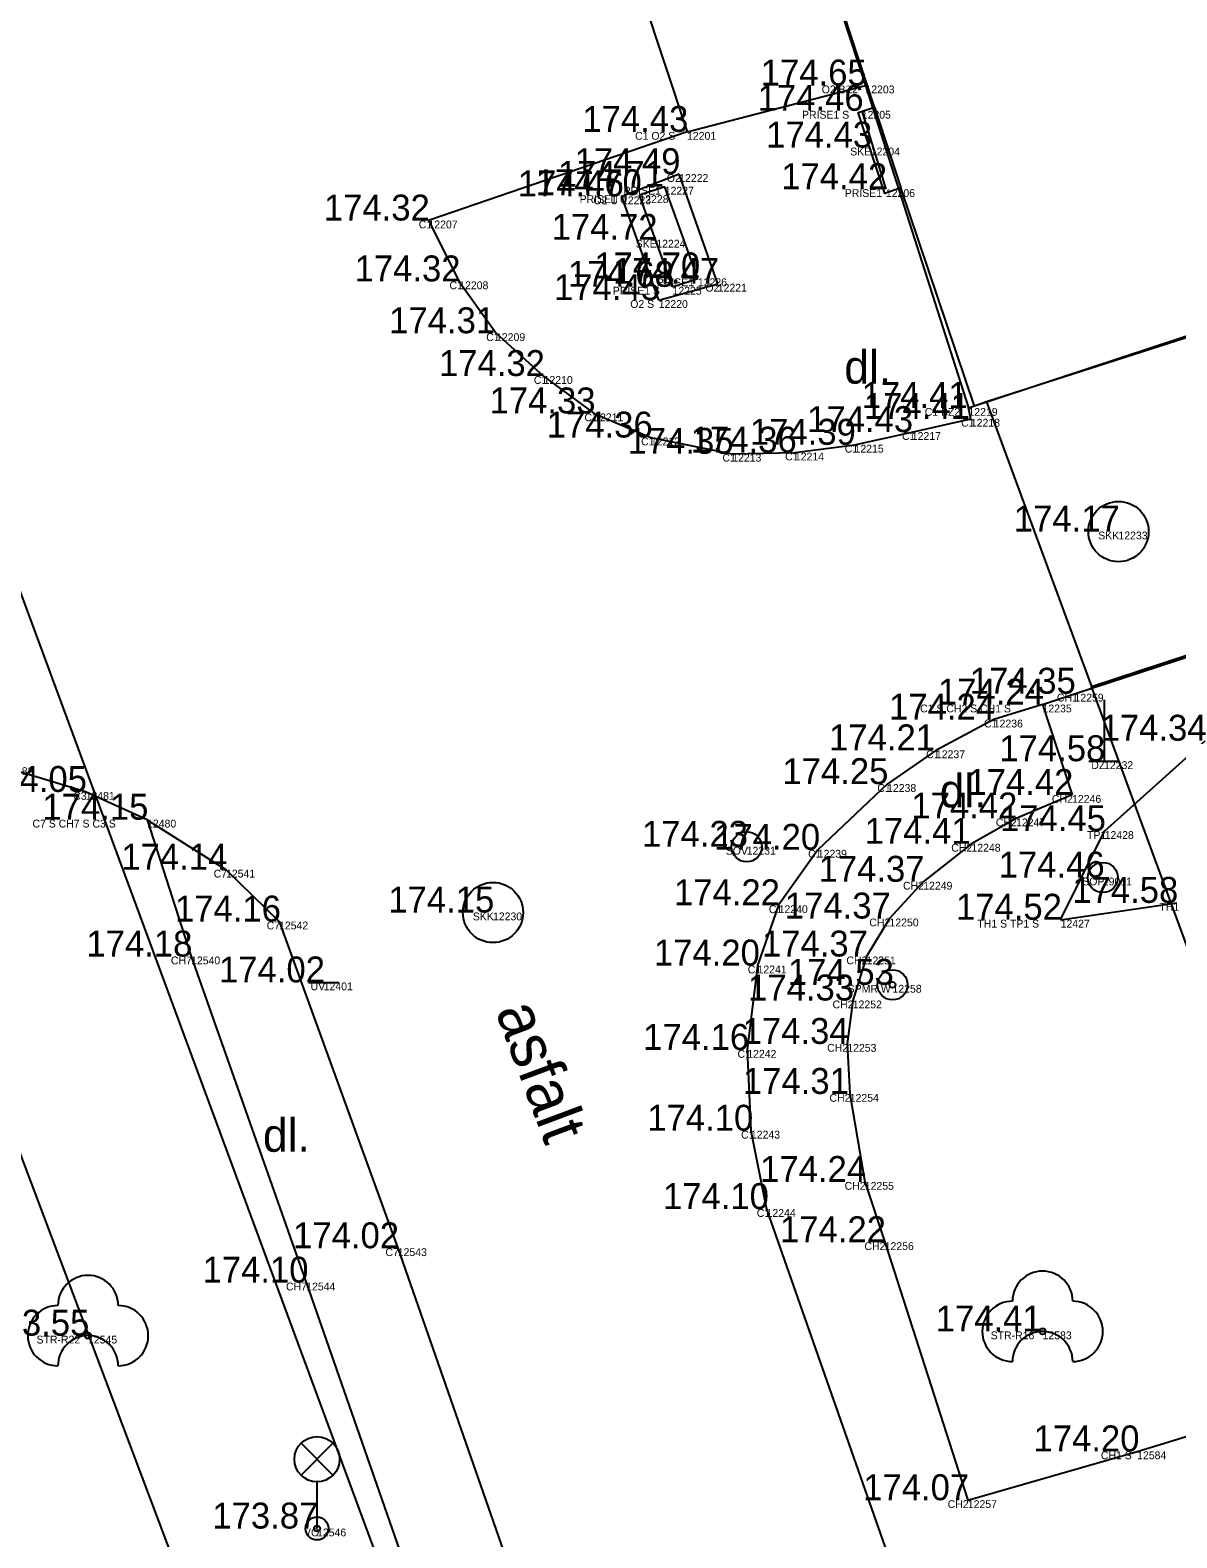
# Model space of a CAD drawing. Extents: x -566117 to -565580, y -1202428 to -1201938.
# Drawn here: x -565742.81 to -565723.78, y -1202226.38 to -1202201.37 of the extents above; entities that cross this region are included whole.
import ezdxf

# ---------------------------------------------------------------- set-up
doc = ezdxf.new("R2010")
doc.units = 0
for name, color, linetype in [('(Construction)', 7, 'Continuous'), ('_0', 7, 'Continuous'), ('Bod', 7, 'Continuous'), ('CIZÍ_NADZEM', 7, 'Continuous'), ('Implicitní', 7, 'Continuous'), ('Kanalizace', 7, 'Continuous'), ('Katastr', 7, 'Continuous'), ('Kod', 7, 'Continuous'), ('Plin', 7, 'Continuous'), ('POMOC_POPIS', 7, 'Continuous'), ('Voda', 7, 'Continuous'), ('Vrstva 61', 7, 'Continuous'), ('Výška', 7, 'Continuous'), ('ZELEŇ', 7, 'Continuous'), ('ZN_DOPLŇKOVÉ', 7, 'Continuous'), ('Zpevněné plohy', 7, 'Continuous'), ('Číslo', 7, 'Continuous')]:
    doc.layers.add(name, color=color, linetype=linetype)

# ---------------------------------------------------------------- blocks, each defined once
blk = doc.blocks.new('A$C69D74C1E')
at = {"layer": 'Katastr'}
for p, q in [((336.13, -134.21), (335.61, -132.63)), ((336.13, -134.21), (336.57, -135.55)), ((339.73, -143.82), (364.58, -135.63)), ((345.24, -136.77), (337.99, -139.1)), ((337.99, -139.1), (339.73, -143.82)), ((368.8, -222.87), (339.73, -143.82))]:
    blk.add_line(p, q, dxfattribs=at)
for points in [[(312.89, -119.52), (313.47, -119.3), (336.92, -182.75)], [(336.57, -135.55), (336.3, -135.64), (335.86, -134.3), (336.13, -134.21)], [(337.99, -139.1), (337.79, -139.17), (336.57, -135.55)], [(334.1, -183.79), (317.19, -138.94), (221, -174.32)]]:
    blk.add_lwpolyline(points, dxfattribs=at)
blk = doc.blocks.new('SP')
at = {"layer": 'Plin'}
blk.add_circle((0, 0), 0.25, dxfattribs=at)
blk = doc.blocks.new('SV')
at = {"layer": 'Voda'}
blk.add_circle((0, 0), 0.25, dxfattribs=at)
blk = doc.blocks.new('SPMR')
at = {"layer": '_0'}
for radius in [0.25, 0.05]:
    blk.add_circle((0, 0), radius, dxfattribs=at)
blk = doc.blocks.new('STROM')
at = {"layer": 'ZELEŇ'}
blk.add_circle((0, 0), 0.05, dxfattribs=at)
for centre, start, end in [((0, 0.5), 0, 180), ((-0.5, 0), 90, 270), ((0.5, 0), 270, 90), ((0, -0.5), 0, 180)]:
    blk.add_arc(centre, 0.5, start, end, dxfattribs=at)
blk = doc.blocks.new('VP')
at = {"layer": 'Kanalizace'}
blk.add_line((-0.25, 0), (0.25, 0), dxfattribs=at)
blk = doc.blocks.new('SAK')
at = {"layer": 'Kanalizace'}
blk.add_circle((0, 0), 0.5, dxfattribs=at)
blk = doc.blocks.new('LA')
at = {"layer": 'CIZÍ_NADZEM'}
for p, q in [((-0.265, 1.415), (0.265, 0.885)), ((-0.265, 0.885), (0.265, 1.415)), ((0, 0), (0, 0.775))]:
    blk.add_line(p, q, dxfattribs=at)
for centre, radius in [((0, 1.15), 0.375), ((0, 0), 0.19), ((0, 0), 0.05)]:
    blk.add_circle(centre, radius, dxfattribs=at)
blk = doc.blocks.new('5.270_1')
at = {"layer": 'ZN_DOPLŇKOVÉ'}
for p, q in [((0, 1.018), (0, 0)), ((-0.25, 0), (0.25, 0))]:
    blk.add_line(p, q, dxfattribs=at)
blk = doc.blocks.new('POINT_DISPLAY')
at = {"layer": 'Implicitní'}
blk.add_line((0, 0), (0, 0), dxfattribs=at)

msp = doc.modelspace()

# ---------------------------------------------------------------- linework, layer by layer
at = {"layer": '(Construction)'}
for p, q in [((-565728.95, -1202202.29), (-565727.24, -1202207.64)), ((-565727.24, -1202207.64), (-565719.64, -1202205.13))]:
    msp.add_line(p, q, dxfattribs=at)
msp.add_lwpolyline([(-565687.26, -1202189.34), (-565694.52, -1202167.23), (-565735.97, -1202180.93), (-565728.95, -1202202.29)], dxfattribs=at)
at = {"layer": '_0'}
for p, q in [((-565729.01, -1202202.71), (-565728.61, -1202204.01)), ((-565732.28, -1202203.97), (-565732.7, -1202204.11)), ((-565732.15, -1202205.63), (-565732.7, -1202204.11)), ((-565731.73, -1202205.49), (-565732.28, -1202203.97)), ((-565732.15, -1202205.63), (-565731.73, -1202205.49))]:
    msp.add_line(p, q, dxfattribs=at)
at = {"layer": 'Zpevněné plohy'}
for p, q in [((-565734.32, -1202195.75), (-565731.91, -1202203.06)), ((-565731.91, -1202203.06), (-565728.95, -1202202.29)), ((-565731.91, -1202203.06), (-565736.2, -1202204.53)), ((-565732.04, -1202203.76), (-565732.99, -1202204.13)), ((-565731.4, -1202205.58), (-565732.04, -1202203.76)), ((-565732.38, -1202205.85), (-565732.99, -1202204.13)), ((-565736.2, -1202204.53), (-565735.69, -1202205.54)), ((-565735.69, -1202205.54), (-565735.08, -1202206.4)), ((-565732.38, -1202205.85), (-565731.4, -1202205.58)), ((-565735.08, -1202206.4), (-565734.29, -1202207.11)), ((-565734.29, -1202207.11), (-565733.45, -1202207.73)), ((-565727.2, -1202207.82), (-565727.24, -1202207.64)), ((-565733.45, -1202207.73), (-565732.51, -1202208.13)), ((-565728.18, -1202208.04), (-565727.2, -1202207.82)), ((-565732.51, -1202208.13), (-565731.16, -1202208.4)), ((-565729.13, -1202208.25), (-565728.18, -1202208.04)), ((-565731.16, -1202208.4), (-565730.12, -1202208.38)), ((-565730.12, -1202208.38), (-565729.13, -1202208.25)), ((-565725.48, -1202212.38), (-565718.15, -1202209.99)), ((-565726.01, -1202212.56), (-565725.48, -1202212.38)), ((-565726.01, -1202212.56), (-565726.82, -1202212.81)), ((-565726.01, -1202212.56), (-565725.52, -1202214.06)), ((-565726.82, -1202212.81), (-565727.78, -1202213.32)), ((-565724.98, -1202214.66), (-565723.31, -1202213.16)), ((-565727.78, -1202213.32), (-565728.59, -1202213.88)), ((-565741.89, -1202214.01), (-565743.24, -1202213.6)), ((-565728.59, -1202213.88), (-565729.74, -1202214.97)), ((-565740.87, -1202214.47), (-565741.89, -1202214.01)), ((-565725.52, -1202214.06), (-565726.45, -1202214.45)), ((-565726.45, -1202214.45), (-565727.19, -1202214.87)), ((-565740.87, -1202214.47), (-565740.14, -1202216.74)), ((-565740.87, -1202214.47), (-565739.56, -1202215.3)), ((-565725.71, -1202216.13), (-565724.98, -1202214.66)), ((-565727.19, -1202214.87), (-565727.99, -1202215.5)), ((-565729.74, -1202214.97), (-565730.39, -1202215.89)), ((-565739.56, -1202215.3), (-565738.68, -1202216.16)), ((-565727.99, -1202215.5), (-565728.55, -1202216.11)), ((-565730.39, -1202215.89), (-565730.74, -1202216.89)), ((-565725.71, -1202216.13), (-565723.78, -1202215.85)), ((-565738.68, -1202216.16), (-565736.71, -1202221.58)), ((-565728.55, -1202216.11), (-565728.93, -1202216.74)), ((-565740.14, -1202216.74), (-565738.23, -1202222.15)), ((-565730.74, -1202216.89), (-565730.91, -1202218.29)), ((-565728.93, -1202216.74), (-565729.16, -1202217.47)), ((-565729.16, -1202217.47), (-565729.25, -1202218.19)), ((-565729.25, -1202218.19), (-565729.21, -1202219.02)), ((-565730.91, -1202218.29), (-565730.85, -1202219.63)), ((-565729.21, -1202219.02), (-565728.96, -1202220.48)), ((-565730.85, -1202219.63), (-565730.59, -1202220.93)), ((-565728.96, -1202220.48), (-565728.63, -1202221.48)), ((-565730.59, -1202220.93), (-565727.88, -1202228.65)), ((-565736.71, -1202221.58), (-565732.03, -1202234.96)), ((-565728.63, -1202221.48), (-565727.25, -1202225.76)), ((-565738.23, -1202222.15), (-565733.57, -1202235.49))]:
    msp.add_line(p, q, dxfattribs=at)
msp.add_lwpolyline([(-565727.25, -1202225.76), (-565724.44, -1202224.95), (-565721, -1202223.9)], dxfattribs=at)

# ---------------------------------------------------------------- block references
at = {"layer": '_0'}
msp.add_blockref('SPMR', (-565728.5, -1202217.21), dxfattribs=at)
at = {"layer": 'Bod'}
for p in [(-565728.95, -1202202.29), (-565729.01, -1202202.71), (-565731.91, -1202203.06), (-565728.86, -1202203.32), (-565732.04, -1202203.76), (-565732.99, -1202204.13), (-565732.7, -1202204.11), (-565732.28, -1202203.97), (-565728.61, -1202204.01), (-565736.2, -1202204.53), (-565732.42, -1202204.85), (-565735.69, -1202205.54), (-565732.15, -1202205.63), (-565731.73, -1202205.49), (-565731.4, -1202205.58), (-565732.38, -1202205.85), (-565735.08, -1202206.4), (-565734.29, -1202207.11), (-565727.24, -1202207.64), (-565733.45, -1202207.73), (-565727.2, -1202207.82), (-565732.51, -1202208.13), (-565728.18, -1202208.04), (-565731.16, -1202208.4), (-565730.12, -1202208.38), (-565729.13, -1202208.25), (-565724.75, -1202209.69), (-565725.48, -1202212.38), (-565726.01, -1202212.56), (-565726.82, -1202212.81), (-565727.78, -1202213.32), (-565724.99, -1202213.5), (-565728.59, -1202213.88), (-565741.89, -1202214.01), (-565725.52, -1202214.06), (-565726.45, -1202214.45), (-565740.87, -1202214.47), (-565724.98, -1202214.66), (-565730.92, -1202214.92), (-565727.19, -1202214.87), (-565729.74, -1202214.97), (-565739.56, -1202215.3), (-565725.01, -1202215.43), (-565727.99, -1202215.5), (-565730.39, -1202215.89), (-565738.68, -1202216.16), (-565735.13, -1202216.01), (-565728.55, -1202216.11), (-565725.71, -1202216.13), (-565740.14, -1202216.74), (-565730.74, -1202216.89), (-565728.93, -1202216.74), (-565737.94, -1202217.17), (-565728.5, -1202217.21), (-565729.16, -1202217.47), (-565729.25, -1202218.19), (-565730.91, -1202218.29), (-565729.21, -1202219.02), (-565730.85, -1202219.63), (-565728.96, -1202220.48), (-565730.59, -1202220.93), (-565736.71, -1202221.58), (-565728.63, -1202221.48), (-565738.23, -1202222.15), (-565726.01, -1202222.96), (-565741.85, -1202223.03), (-565724.44, -1202224.95), (-565727.25, -1202225.76), (-565738.05, -1202226.23)]:
    msp.add_blockref('POINT_DISPLAY', p, dxfattribs=at)
at = {"layer": 'CIZÍ_NADZEM'}
msp.add_blockref('LA', (-565738.05, -1202226.23), dxfattribs=at)
at = {"layer": 'Implicitní'}
msp.add_blockref('A$C69D74C1E', (-566064.93, -1202068.44), dxfattribs=at)
at = {"layer": 'Kanalizace'}
for p in [(-565724.75, -1202209.69), (-565735.13, -1202216.01)]:
    msp.add_blockref('SAK', p, dxfattribs=at)
at = {"layer": 'Plin'}
msp.add_blockref('SP', (-565725.01, -1202215.43), dxfattribs=at)
at = {"layer": 'Voda'}
msp.add_blockref('SV', (-565730.92, -1202214.92), dxfattribs=at)
at = {"layer": 'Vrstva 61'}
msp.add_blockref('VP', (-565737.94, -1202217.17), dxfattribs=at)
at = {"layer": 'ZELEŇ'}
for p in [(-565726.01, -1202222.96), (-565741.85, -1202223.03)]:
    msp.add_blockref('STROM', p, dxfattribs=at)
at = {"layer": 'ZN_DOPLŇKOVÉ'}
msp.add_blockref('5.270_1', (-565724.99, -1202213.5), dxfattribs=at)

# ---------------------------------------------------------------- texts
at = {"layer": 'Kod'}
for s, p in [('O2 BZ2', (-565729.675, -1202202.42)), ('PRISE1 S', (-565730.002, -1202202.84)), ('C1 O2 S', (-565732.772, -1202203.19)), ('SKE', (-565729.202, -1202203.45)), ('O2', (-565732.245, -1202203.89)), ('PRISE1 U', (-565733.692, -1202204.24)), ('O2 U', (-565733.462, -1202204.26)), ('PRISE1', (-565732.962, -1202204.1)), ('PRISE1', (-565729.292, -1202204.14)), ('C1', (-565736.362, -1202204.66)), ('SKE', (-565732.762, -1202204.98)), ('C1', (-565735.852, -1202205.67)), ('PRISE1 S', (-565733.142, -1202205.76)), ('PRISE1', (-565732.412, -1202205.62)), ('O2', (-565731.605, -1202205.71)), ('O2 S', (-565732.852, -1202205.98)), ('C1', (-565735.242, -1202206.53)), ('C1', (-565734.452, -1202207.24)), ('C1 BZ2', (-565727.965, -1202207.77)), ('C1', (-565733.612, -1202207.86)), ('C1', (-565727.362, -1202207.95)), ('C1', (-565732.672, -1202208.26)), ('C1', (-565728.342, -1202208.17)), ('C1', (-565731.322, -1202208.53)), ('C1', (-565730.282, -1202208.51)), ('C1', (-565729.292, -1202208.38)), ('SKK', (-565725.085, -1202209.82)), ('CH1', (-565725.772, -1202212.51)), ('C1 S CH2 S CH1 S', (-565728.042, -1202212.69)), ('C1', (-565726.982, -1202212.94)), ('C1', (-565727.942, -1202213.45)), ('DZ', (-565725.201, -1202213.63)), ('C1', (-565728.752, -1202214.01)), ('C3', (-565742.095, -1202214.14)), ('CH2', (-565725.855, -1202214.19)), ('CH2', (-565726.785, -1202214.58)), ('C7 S CH7 S C3 S', (-565742.772, -1202214.6)), ('TP1', (-565725.272, -1202214.79)), ('SOV', (-565731.267, -1202215.05)), ('CH2', (-565727.525, -1202215)), ('C1', (-565729.902, -1202215.1)), ('C7', (-565739.765, -1202215.43)), ('SOP', (-565725.351, -1202215.56)), ('CH2', (-565728.325, -1202215.63)), ('C1', (-565730.552, -1202216.02)), ('TH1', (-565724.072, -1202215.98)), ('C7', (-565738.885, -1202216.29)), ('SKK', (-565735.465, -1202216.14)), ('CH2', (-565728.885, -1202216.24)), ('TH1 S TP1 S', (-565727.092, -1202216.26)), ('CH7', (-565740.475, -1202216.87)), ('C1', (-565730.902, -1202217.02)), ('CH2', (-565729.265, -1202216.87)), ('UV', (-565738.157, -1202217.3)), ('SPMR W', (-565729.244, -1202217.34)), ('CH2', (-565729.495, -1202217.6)), ('CH2', (-565729.585, -1202218.32)), ('C1', (-565731.072, -1202218.42)), ('CH2', (-565729.545, -1202219.15)), ('C1', (-565731.012, -1202219.76)), ('CH2', (-565729.295, -1202220.61)), ('C1', (-565730.752, -1202221.06)), ('C7', (-565736.915, -1202221.71)), ('CH2', (-565728.965, -1202221.61)), ('CH7', (-565738.565, -1202222.28)), ('STR-R16', (-565726.871, -1202223.09)), ('STR-R22', (-565742.705, -1202223.16)), ('CH1 S', (-565725.042, -1202225.08)), ('CH2', (-565727.585, -1202225.89)), ('VO', (-565738.266, -1202226.36))]:
    msp.add_text(s, height=0.13, dxfattribs=at).set_placement(p)
at = {"layer": 'POMOC_POPIS'}
for p in [(-565729.3, -1202207.236), (-565727.717, -1202214.265), (-565738.947, -1202219.979)]:
    msp.add_text('dl.', height=0.55, dxfattribs=at).set_placement(p)
msp.add_text('asfalt', height=0.75, rotation=290.4548, dxfattribs=at).set_placement((-565735.093, -1202217.645))
at = {"layer": 'Výška'}
for s, p in [('174.65 ', (-565730.687, -1202202.29)), ('174.46 ', (-565730.738, -1202202.71)), ('174.43 ', (-565733.647, -1202203.06)), ('174.43 ', (-565730.597, -1202203.32)), ('174.49 ', (-565733.777, -1202203.76)), ('174.46 ', (-565734.718, -1202204.13)), ('174.70 ', (-565734.42, -1202204.11)), ('174.71 ', (-565734.053, -1202203.97)), ('174.42 ', (-565730.347, -1202204.01)), ('174.32 ', (-565737.937, -1202204.53)), ('174.72 ', (-565734.157, -1202204.85)), ('174.32 ', (-565737.427, -1202205.54)), ('174.68 ', (-565733.887, -1202205.63)), ('174.70 ', (-565733.45, -1202205.49)), ('174.47 ', (-565733.137, -1202205.58)), ('174.45 ', (-565734.117, -1202205.85)), ('174.31 ', (-565736.853, -1202206.4)), ('174.32 ', (-565736.027, -1202207.11)), ('174.33 ', (-565735.187, -1202207.73)), ('174.41 ', (-565729.013, -1202207.64)), ('174.41 ', (-565728.973, -1202207.82)), ('174.36 ', (-565734.238, -1202208.13)), ('174.43 ', (-565729.917, -1202208.04)), ('174.36 ', (-565731.848, -1202208.38)), ('174.39 ', (-565730.867, -1202208.25)), ('174.35 ', (-565732.897, -1202208.4)), ('174.17 ', (-565726.487, -1202209.69)), ('174.35 ', (-565727.217, -1202212.38)), ('174.24 ', (-565727.747, -1202212.56)), ('174.24 ', (-565728.557, -1202212.81)), ('174.21 ', (-565729.553, -1202213.32)), ('174.34 ', (-565725.047, -1202213.16)), ('174.58 ', (-565726.727, -1202213.5)), ('174.25 ', (-565730.327, -1202213.88)), ('174.05 ', (-565743.627, -1202214.01)), ('174.42 ', (-565727.257, -1202214.06)), ('174.15 ', (-565742.607, -1202214.47)), ('174.42 ', (-565728.187, -1202214.45)), ('174.41 ', (-565728.963, -1202214.87)), ('174.45 ', (-565726.717, -1202214.66)), ('174.23 ', (-565732.657, -1202214.92)), ('174.20 ', (-565731.46, -1202214.97)), ('174.14 ', (-565741.297, -1202215.3)), ('174.37 ', (-565729.727, -1202215.5)), ('174.46 ', (-565726.738, -1202215.43)), ('174.22 ', (-565732.127, -1202215.89)), ('174.58 ', (-565725.517, -1202215.85)), ('174.15 ', (-565736.867, -1202216.01)), ('174.37 ', (-565730.287, -1202216.11)), ('174.52 ', (-565727.447, -1202216.13)), ('174.16 ', (-565740.408, -1202216.16)), ('174.18 ', (-565741.877, -1202216.74)), ('174.20 ', (-565732.46, -1202216.89)), ('174.37 ', (-565730.667, -1202216.74)), ('174.02 ', (-565739.677, -1202217.17)), ('174.53 ', (-565730.237, -1202217.21)), ('174.33 ', (-565730.897, -1202217.47)), ('174.16 ', (-565732.638, -1202218.29)), ('174.34 ', (-565730.987, -1202218.19)), ('174.31 ', (-565730.983, -1202219.02)), ('174.10 ', (-565732.57, -1202219.63)), ('174.24 ', (-565730.697, -1202220.48)), ('174.10 ', (-565732.31, -1202220.93)), ('174.02 ', (-565738.447, -1202221.58)), ('174.22 ', (-565730.367, -1202221.48)), ('174.10 ', (-565739.95, -1202222.15)), ('173.55 ', (-565743.587, -1202223.03)), ('174.41 ', (-565727.783, -1202222.96)), ('174.20 ', (-565726.16, -1202224.95)), ('174.07 ', (-565728.987, -1202225.76)), ('173.87 ', (-565739.787, -1202226.23))]:
    msp.add_text(s, height=0.43, dxfattribs=at).set_placement(p)
at = {"layer": 'Číslo'}
for s, p in [('12203', (-565728.95, -1202202.42)), ('12205', (-565729.01, -1202202.84)), ('12201', (-565731.91, -1202203.19)), ('12204', (-565728.86, -1202203.45)), ('12222', (-565732.04, -1202203.89)), ('12223', (-565732.99, -1202204.26)), ('12228', (-565732.7, -1202204.24)), ('12227', (-565732.28, -1202204.1)), ('12206', (-565728.61, -1202204.14)), ('12207', (-565736.2, -1202204.66)), ('12224', (-565732.42, -1202204.98)), ('12208', (-565735.69, -1202205.67)), ('12225', (-565732.15, -1202205.76)), ('12226', (-565731.73, -1202205.62)), ('12221', (-565731.4, -1202205.71)), ('12220', (-565732.38, -1202205.98)), ('12209', (-565735.08, -1202206.53)), ('12210', (-565734.29, -1202207.24)), ('12219', (-565727.24, -1202207.77)), ('12211', (-565733.45, -1202207.86)), ('12218', (-565727.2, -1202207.95)), ('12212', (-565732.51, -1202208.26)), ('12217', (-565728.18, -1202208.17)), ('12213', (-565731.16, -1202208.53)), ('12214', (-565730.12, -1202208.51)), ('12215', (-565729.13, -1202208.38)), ('12233', (-565724.75, -1202209.82)), ('12259', (-565725.48, -1202212.51)), ('12235', (-565726.01, -1202212.69)), ('12236', (-565726.82, -1202212.94)), ('12237', (-565727.78, -1202213.45)), ('12482', (-565743.24, -1202213.73)), ('12232', (-565724.99, -1202213.63)), ('12238', (-565728.59, -1202214.01)), ('12481', (-565741.89, -1202214.14)), ('12246', (-565725.52, -1202214.19)), ('12247', (-565726.45, -1202214.58)), ('12480', (-565740.87, -1202214.6)), ('12428', (-565724.98, -1202214.79)), ('12231', (-565730.92, -1202215.05)), ('12248', (-565727.19, -1202215)), ('12239', (-565729.74, -1202215.1)), ('12541', (-565739.56, -1202215.43)), ('19011', (-565725.01, -1202215.56)), ('12249', (-565727.99, -1202215.63)), ('12240', (-565730.39, -1202216.02)), ('12542', (-565738.68, -1202216.29)), ('12230', (-565735.13, -1202216.14)), ('12250', (-565728.55, -1202216.24)), ('12427', (-565725.71, -1202216.26)), ('12540', (-565740.14, -1202216.87)), ('12241', (-565730.74, -1202217.02)), ('12251', (-565728.93, -1202216.87)), ('12401', (-565737.94, -1202217.3)), ('12258', (-565728.5, -1202217.34)), ('12252', (-565729.16, -1202217.6)), ('12253', (-565729.25, -1202218.32)), ('12242', (-565730.91, -1202218.42)), ('12254', (-565729.21, -1202219.15)), ('12243', (-565730.85, -1202219.76)), ('12255', (-565728.96, -1202220.61)), ('12244', (-565730.59, -1202221.06)), ('12543', (-565736.71, -1202221.71)), ('12256', (-565728.63, -1202221.61)), ('12544', (-565738.23, -1202222.28)), ('12583', (-565726.01, -1202223.09)), ('12545', (-565741.85, -1202223.16)), ('12584', (-565724.44, -1202225.08)), ('12257', (-565727.25, -1202225.89)), ('12546', (-565738.05, -1202226.36))]:
    msp.add_text(s, height=0.13, dxfattribs=at).set_placement(p)

doc.saveas('drawing.dxf')
